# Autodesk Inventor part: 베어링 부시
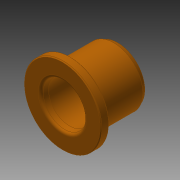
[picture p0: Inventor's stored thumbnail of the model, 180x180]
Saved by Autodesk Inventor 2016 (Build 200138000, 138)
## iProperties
Created: 2022-03
Part Number: 베어링 부시
Material: 황동, 연질
Document SubType Name: Modeling
Designer: mdu-01
Density: 1 g/cm^3
Appearance: 주황색
Author: mdu-01
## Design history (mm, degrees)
sketch "스케치1"
  geometry: L1 (0, 0)-(0, -20); L2 (7.941, 0)-(14, 0); L3 (14, 0)-(14, -3); L4 (14, -3)-(10.5, -3); L5 (10.5, -3)-(10.5, -18.6); L6 (9.844, -20)-(7.606, -20); L7 (7.5, -2.5)-(7.5, -19.4); L8 (7.5, -2.5)-(7.941, 0); L9 (7.5, -19.4)-(7.606, -20); L10 (10.5, -18.6)-(9.844, -20)
  constraints: 20 end point, 3 perpendicular, 2 horizontal alignment, 2 parallel, 1 horizontal, 1 vertical
  dimensions: "d0" = 21 diameter of L5 L1; "d2" = 28 diameter of L3 L1; "d3" = 20 distance of L1.start L1.end; "d4" = 3 distance of L2.end L3.end; "d5" = 15 diameter of L7 L1; "d6" = 10 deg angle of L7 L9; "d7" = 0.6 distance from line of L7.end L6; "d8" = 1.4 vertical distance of L5.end L6.start; "d9" = 25.0978 deg angle of L5 L10; "d10" = 10 deg angle of L7 L8; "d11" = 2.5 vertical distance of L7.start L2.start
revolve "회전1" sketch "스케치1" stored, may be unused: angle "d12" = 90 deg
chamfer "모따기1" distance "d13" = 0.3; stored, may be unused: second distance "d14" = 2, angle "d15" = 45 deg
fillet "모깎기1" dims "d16" = 0.3, "d17" = 1
node "솔리드1"
